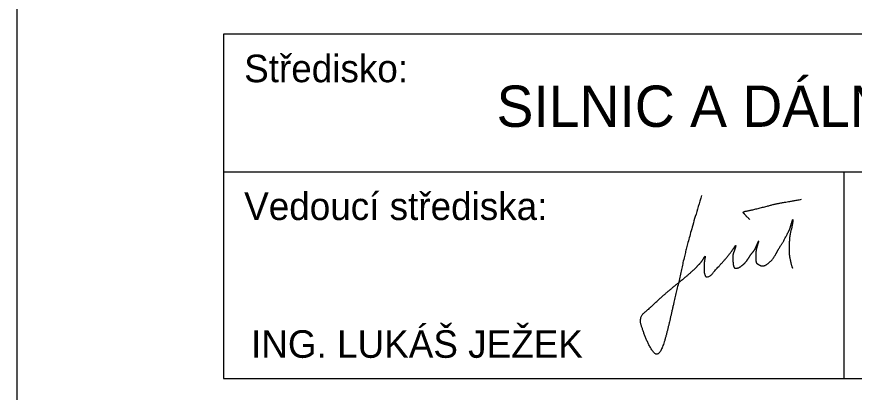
# Model space of a CAD drawing. Extents: x 1619 to 1829, y 760 to 1057.
# Drawn here: x 1618.7 to 1679.4, y 833.4 to 860.7 of the extents above; entities that cross this region are included whole.
import ezdxf

# ---------------------------------------------------------------- set-up
doc = ezdxf.new("R2010")
doc.units = 0
doc.layers.add('120_ZPEVNENI', color=7, linetype='Continuous')

msp = doc.modelspace()

# ---------------------------------------------------------------- linework, layer by layer
at = {"layer": '120_ZPEVNENI'}
for p, q in [((1633.65, 849.446), (1813.65, 849.446)), ((1678.65, 849.446), (1678.65, 834.446))]:
    msp.add_line(p, q, dxfattribs=at)
for points in [[(1618.65, 759.931), (1828.65, 759.931), (1828.65, 1056.931), (1618.65, 1056.931)], [(1633.65, 834.446), (1813.65, 834.446), (1813.65, 859.446), (1633.65, 859.446)]]:
    msp.add_lwpolyline(points, close=True, dxfattribs=at)
for points in [[(1668.339, 847.734), (1667.91, 846.319), (1667.383, 844.461), (1667.081, 843.272), (1666.848, 842.228), (1666.592, 841.058), (1666.343, 840.028), (1666.109, 838.999), (1665.911, 838.145), (1665.633, 837.067), (1665.335, 836.33), (1665.049, 836.157), (1664.766, 836.436), (1664.45, 837.01), (1664.213, 837.573), (1664.024, 838.108), (1663.87, 838.598), (1663.997, 839.074), (1664.429, 839.412), (1664.915, 839.879), (1665.773, 840.664), (1666.978, 841.643), (1667.571, 842.147), (1667.984, 842.547), (1668.351, 842.929), (1668.647, 843.446), (1668.525, 842.892), (1668.509, 842.392), (1668.549, 841.989), (1668.688, 841.763), (1669.037, 841.925), (1669.268, 842.235), (1669.634, 842.632), (1670.16, 843.211), (1670.565, 843.735), (1670.865, 844.205), (1670.748, 843.808), (1670.626, 843.504), (1670.595, 843.253), (1670.623, 842.786), (1670.67, 842.539), (1670.754, 842.435), (1670.972, 842.449), (1671.183, 842.571), (1671.495, 842.824), (1671.754, 843.183), (1671.953, 843.507), (1672.168, 843.726), (1672.402, 844.247), (1672.516, 844.509), (1672.334, 843.943), (1672.262, 843.557), (1672.265, 843.261), (1672.285, 842.934), (1672.308, 842.811), (1672.761, 842.542), (1673.274, 842.839), (1673.665, 843.331), (1673.873, 843.765), (1674.216, 844.285), (1674.58, 844.978), (1674.735, 845.253), (1674.85, 845.666), (1674.994, 846.127), (1674.908, 845.482), (1674.714, 844.78), (1674.694, 843.877), (1674.694, 843.362), (1674.865, 842.608), (1674.937, 842.441)], [(1671.837, 845.972), (1671.437, 846.384), (1671.318, 846.549), (1671.766, 846.623), (1672.704, 846.852), (1673.78, 847.136), (1674.537, 847.26), (1675.587, 847.449)]]:
    msp.add_open_spline(points, degree=2, dxfattribs=at)

# ---------------------------------------------------------------- texts
for s, height, p in [('Středisko:', 2, (1635.15, 855.946)), ('SILNIC A DÁLNIC', 3, (1653.462, 852.705)), ('Vedoucí střediska:', 2, (1635.15, 845.946)), ('ING. LUKÁŠ JEŽEK', 2, (1635.65, 835.946))]:
    msp.add_text(s, height=height, dxfattribs=at).set_placement(p)

doc.saveas('drawing.dxf')
